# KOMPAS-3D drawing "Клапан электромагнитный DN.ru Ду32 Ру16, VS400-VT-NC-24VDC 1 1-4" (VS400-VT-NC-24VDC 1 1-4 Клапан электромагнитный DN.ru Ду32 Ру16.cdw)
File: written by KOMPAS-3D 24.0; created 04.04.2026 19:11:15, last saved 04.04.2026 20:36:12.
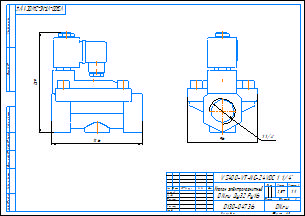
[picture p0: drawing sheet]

Document properties: c3d_UniqueCompID: ef56311e-7521-43dc-8291-0e6108b3d81d; Обозначение: VS400-ET-NC-220VAC 1; Наименование: Клапан электромагнитный DN.ru Ду25 Ру16; Автор: artio; Класс точности: c; Знак неуказанной шероховатости: Шероховатость не задана; Рассекать на разрезах: Да; c3d_UniqueCompID: ef56311e-7521-43dc-8291-0e6108b3d81d; Обозначение: VS400-ET-NC-220VAC 1-2; Наименование: Клапан электромагнитный DN.ru Ду15 Ру16; Автор: artio; Класс точности: c; Знак неуказанной шероховатости: Шероховатость не задана; Рассекать на разрезах: Да; c3d_UniqueCompID: ef56311e-7521-43dc-8291-0e6108b3d81d; Обозначение: VS400-ET-NC-220VAC 3-4; Наименование: Клапан электромагнитный DN.ru Ду20 Ру16; Автор: artio; Класс точности: c; Знак неуказанной шероховатости: Шероховатость не задана; Рассекать на разрезах: Да; c3d_UniqueCompID: ef56311e-7521-43dc-8291-0e6108b3d81d; Обозначение: VS400-ET-NC-220VAC 1 1-4; Наименование: Клапан электромагнитный DN.ru Ду32 Ру16; Автор: artio; Класс точности: c; Знак неуказанной шероховатости: Шероховатость не задана; Рассекать на разрезах: Да; c3d_UniqueCompID: ef56311e-7521-43dc-8291-0e6108b3d81d; Обозначение: VS400-ET-NC-220VAC 3-8; Наименование: Клапан электромагнитный DN.ru Ду10 Ру16; Автор: artio; Класс точности: c; Знак неуказанной шероховатости: Шероховатость не задана; Рассекать на разрезах: Да; Автор: artio; Форматы листов документа: A3; Полное имя файла: VS400-VT-NC-24VDC 1 1-4 Клапан электромагнитный DN.ru Ду32 Ру16.m3d; Масса: 2.569; Наименование: Клапан электромагнитный DN.ru Ду32 Ру16; Количество листов документа: 1; Примечание: D130-04736

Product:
- Body: Тело 1  | qty 1
    Масса: 4.144257
- Part/product: Клапан электромагнитный DN.ru Ду32 Ру16  | designation VS400-VT-NC-24VDC 1 1-4
    Масса: 2.569
    Раздел спецификации: Прочие изделия
    Примечание: D130-04736
    additional columns: ef56311e-7521-43dc-8291-0e6108b3d81d; VS400-ET-NC-220VAC 1 1-4; artio; c; Шероховатость не задана; Да

Views: Вид 1, Спереди
Referenced files in C:\Users\artio\OneDrive\Рабочий стол\Клапан электромагнитный DN.ru\VS400-ET-NC\VS400-ET-NC-24VDC\: VS400-ET-NC-24VDC 3-8 Клапан электромагнитный DN.ru Ду10 Ру16.m3d
Referenced files in C:\Users\artio\OneDrive\Рабочий стол\Клапан электромагнитный DN.ru\VS400-VT-NC\VS400-VT-NC-24VDC\: VS400-VT-NC-24VDC 1 1-4 Клапан электромагнитный DN.ru Ду32 Ру16.m3d
Referenced files in C:\Users\artio\OneDrive\Рабочий стол\Клапан электромагнитный DN.ru\VS400-ET-NC\: VS400-ET-NC-24VDC 3-8 Клапан электромагнитный DN.ru Ду10 Ру16.cdw
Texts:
  VS400-VT-NC-24VDC 1 1-4
  Клапан электромагнитный
  DN.ru Ду32 Ру16
  VS400-VT-NC-24VDC 1 1/4"
  VS400-VT-NC-24VDC 1 1/4"-
  Клапан электромагнитный DN.ru Ду32 Ру16
  VS400-VT-NC-24VDC 1 1-4 Клапан электромагнитный DN.ru Ду32 Ру16
Dimensions and other numbers on the sheet: 0; 3; 2; 4; 96; 1 1/4"; 1:1; 1; 2,57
